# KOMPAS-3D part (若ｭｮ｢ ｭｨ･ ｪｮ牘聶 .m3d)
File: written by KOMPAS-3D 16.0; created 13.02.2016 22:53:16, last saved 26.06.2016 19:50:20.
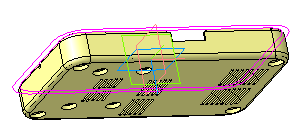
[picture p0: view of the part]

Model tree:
1. Эскиз:1
2. Операция выдавливания:1
     Расстояние 1 = 30
3. Эскиз:3
4. Вырезать элемент выдавливания:1
     Расстояние 1 = 28
5. Скругление:1
     Радиус = 5
6. Эскиз:4
7. Вырезать элемент выдавливания:2
     Расстояние 1 = 3
8. Эскиз:7
9. Эскиз:8
10. Вырезать элемент выдавливания:5
     Расстояние 1 = 12
11. Операция выдавливания:2
     Расстояние 1 = 10
12. Эскиз:9
13. Операция выдавливания:3
     Расстояние 1 = 30
14. Эскиз:10
15. Операция выдавливания:4
     Расстояние 1 = 30
16. Вырезать элемент выдавливания:10
     Расстояние 1 = 42
17. Вырезать элемент выдавливания:11
     Расстояние 1 = 42
18. Вырезать элемент выдавливания:12
     Расстояние 1 = 42
19. Вырезать элемент выдавливания:13
     Расстояние 1 = 42
20. Эскиз:14
21. Операция выдавливания:5
     Расстояние 1 = 10
22. Эскиз:15
23. Операция выдавливания:6
     Расстояние 1 = 28
24. Эскиз:16
25. Вырезать элемент выдавливания:14
     Расстояние 2 = 30; Расстояние 1 = 32
26. Эскиз:17
27. Операция выдавливания:7
     Расстояние 1 = 26
28. Эскиз:18
29. Вырезать элемент выдавливания:15
     Расстояние 2 = 30; Расстояние 1 = 3
30. Эскиз:19
31. Вырезать элемент выдавливания:16
     Расстояние 2 = 30; Расстояние 1 = 43
32. Эскиз:20
33. Вырезать элемент выдавливания:17
     Расстояние 2 = 30; Расстояние 1 = 4
34. Эскиз:21
35. Вырезать элемент выдавливания:18
     Расстояние 2 = 30; Расстояние 1 = 28
36. Эскиз:22
37. Операция выдавливания:8
     Расстояние 1 = 18
38. Эскиз:23
39. Вырезать элемент выдавливания:19
     Расстояние 1 = 6
40. Эскиз:24
41. Вырезать элемент выдавливания:20  (labels: Фторопласт-4  ГОСТ 10007-80 Е)
     Расстояние 1 = 10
